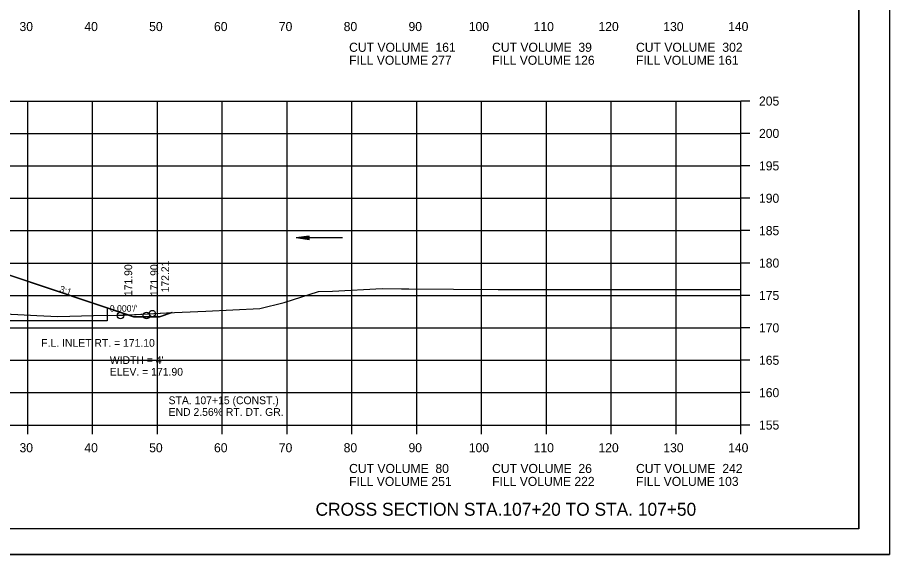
# Model space of a CAD drawing. Extents: x 1372132 to 1372465, y 380083 to 381790.
# Drawn here: x 1372330.4 to 1372464.9, y 380936.8 to 381019.7 of the extents above; entities that cross this region are included whole.
import ezdxf

# ---------------------------------------------------------------- set-up
doc = ezdxf.new("R2010")
doc.units = 0
for name, color, linetype in [('Default', 7, 'Continuous'), ('R_Axis', 7, 'Continuous'), ('R_Axis Annot', 7, 'Continuous'), ('R_Border', 7, 'Continuous'), ('R_Dimension', 7, 'Continuous'), ('R_Draft', 7, 'Continuous'), ('R_Exist Surface', 7, 'Continuous'), ('R_Fin Surface', 7, 'Continuous'), ('R_Grid', 7, 'Continuous'), ('R_No Plot', 7, 'Continuous'), ('R_Xsect Elev', 7, 'Continuous'), ('R_Xsect Slope', 7, 'Continuous')]:
    doc.layers.add(name, color=color, linetype=linetype)

msp = doc.modelspace()

# ---------------------------------------------------------------- linework, layer by layer
at = {"layer": 'Default'}
for p, q in [((1372344.25, 380974.92), (1372344.25, 380972.92)), ((1372344.25, 380972.92), (1372302.01, 380972.88))]:
    msp.add_line(p, q, dxfattribs=at)
at = {"layer": 'R_Axis'}
for p, q in [((1372442.01, 380956.83), (1372442.01, 381006.83)), ((1372443.41, 381006.83), (1372442.01, 381006.83)), ((1372443.41, 381001.83), (1372442.01, 381001.83)), ((1372443.41, 380996.83), (1372442.01, 380996.83)), ((1372443.41, 380991.83), (1372442.01, 380991.83)), ((1372443.41, 380986.83), (1372442.01, 380986.83)), ((1372443.41, 380981.83), (1372442.01, 380981.83)), ((1372443.41, 380976.83), (1372442.01, 380976.83)), ((1372443.41, 380971.83), (1372442.01, 380971.83)), ((1372443.41, 380966.83), (1372442.01, 380966.83)), ((1372443.41, 380961.83), (1372442.01, 380961.83)), ((1372162.01, 380956.83), (1372442.01, 380956.83)), ((1372332.01, 380955.43), (1372332.01, 380956.83)), ((1372342.01, 380955.43), (1372342.01, 380956.83)), ((1372352.01, 380955.43), (1372352.01, 380956.83)), ((1372362.01, 380955.43), (1372362.01, 380956.83)), ((1372372.01, 380955.43), (1372372.01, 380956.83)), ((1372382.01, 380955.43), (1372382.01, 380956.83)), ((1372392.01, 380955.43), (1372392.01, 380956.83)), ((1372402.01, 380955.43), (1372402.01, 380956.83)), ((1372412.01, 380955.43), (1372412.01, 380956.83)), ((1372422.01, 380955.43), (1372422.01, 380956.83)), ((1372432.01, 380955.43), (1372432.01, 380956.83)), ((1372442.01, 380955.43), (1372442.01, 380956.83)), ((1372443.41, 380956.83), (1372442.01, 380956.83))]:
    msp.add_line(p, q, dxfattribs=at)
at = {"layer": 'R_Border'}
for q in [(1372460.19, 381146.29), (1372144.01, 380940.83)]:
    msp.add_line((1372460.19, 380940.83), q, dxfattribs=at)
at = {"layer": 'R_Dimension'}
for p, q in [((1372375.41, 380986), (1372373.41, 380985.7)), ((1372375.41, 380986), (1372373.41, 380985.7)), ((1372375.41, 380985.4), (1372373.41, 380985.7)), ((1372375.41, 380985.4), (1372373.41, 380985.7)), ((1372375.41, 380985.95), (1372373.75, 380985.7)), ((1372375.41, 380985.95), (1372373.75, 380985.7)), ((1372375.41, 380985.45), (1372373.75, 380985.7)), ((1372375.41, 380985.45), (1372373.75, 380985.7)), ((1372375.41, 380985.9), (1372374.09, 380985.7)), ((1372375.41, 380985.9), (1372374.09, 380985.7)), ((1372375.41, 380985.5), (1372374.09, 380985.7)), ((1372375.41, 380985.5), (1372374.09, 380985.7)), ((1372375.41, 380985.85), (1372374.43, 380985.7)), ((1372375.41, 380985.85), (1372374.43, 380985.7)), ((1372375.41, 380985.55), (1372374.43, 380985.7)), ((1372375.41, 380985.55), (1372374.43, 380985.7)), ((1372375.41, 380985.8), (1372374.76, 380985.7)), ((1372375.41, 380985.8), (1372374.76, 380985.7)), ((1372375.41, 380985.6), (1372374.76, 380985.7)), ((1372375.41, 380985.6), (1372374.76, 380985.7)), ((1372375.41, 380985.75), (1372375.1, 380985.7)), ((1372375.41, 380985.75), (1372375.1, 380985.7)), ((1372375.41, 380985.65), (1372375.1, 380985.7)), ((1372375.41, 380985.65), (1372375.1, 380985.7)), ((1372375.41, 380985.4), (1372375.41, 380986)), ((1372375.41, 380985.4), (1372375.41, 380986))]:
    msp.add_line(p, q, dxfattribs=at)
at = {"layer": 'R_Draft'}
msp.add_line((1372380.55, 380985.7), (1372373.41, 380985.7), dxfattribs=at)
at = {"layer": 'R_Exist Surface'}
msp.add_lwpolyline([(1372320.59, 380974.4), (1372333.44, 380973.73), (1372336.66, 380973.6), (1372342.14, 380973.75), (1372345.89, 380973.77), (1372346.54, 380973.79), (1372346.82, 380973.8), (1372353.41, 380974.15), (1372359.48, 380974.38), (1372367.82, 380974.82), (1372371.58, 380975.74), (1372376.85, 380977.43), (1372379.01, 380977.49), (1372386.7, 380977.89), (1372389.66, 380977.86), (1372390.32, 380977.86), (1372390.82, 380977.86), (1372404.58, 380977.77), (1372404.93, 380977.77), (1372417.61, 380977.76), (1372417.98, 380977.77), (1372430.63, 380977.76), (1372431.03, 380977.76), (1372442.01, 380977.75)], dxfattribs=at)
at = {"layer": 'R_Fin Surface'}
msp.add_lwpolyline([(1372247.03, 380973.53), (1372248.08, 380973.18), (1372256.08, 380973.18), (1372277.01, 380980.16), (1372282.65, 380981.57), (1372287.01, 380982.66), (1372291.01, 380982.82), (1372302.01, 380983.04), (1372313.01, 380982.82), (1372317.01, 380982.66), (1372321.38, 380981.57), (1372329.04, 380979.99), (1372348.35, 380973.55), (1372352.35, 380973.55), (1372354.28, 380974.19)], dxfattribs=at)
at = {"layer": 'R_Grid'}
for p, q in [((1372162.01, 381006.83), (1372442.01, 381006.83)), ((1372332.01, 380956.83), (1372332.01, 381006.83)), ((1372342.01, 380956.83), (1372342.01, 381006.83)), ((1372352.01, 380956.83), (1372352.01, 381006.83)), ((1372362.01, 380956.83), (1372362.01, 381006.83)), ((1372372.01, 380956.83), (1372372.01, 381006.83)), ((1372382.01, 380956.83), (1372382.01, 381006.83)), ((1372392.01, 380956.83), (1372392.01, 381006.83)), ((1372402.01, 380956.83), (1372402.01, 381006.83)), ((1372412.01, 380956.83), (1372412.01, 381006.83)), ((1372422.01, 380956.83), (1372422.01, 381006.83)), ((1372432.01, 380956.83), (1372432.01, 381006.83)), ((1372442.01, 380956.83), (1372442.01, 381006.83)), ((1372162.01, 381001.83), (1372442.01, 381001.83)), ((1372162.01, 380996.83), (1372442.01, 380996.83)), ((1372162.01, 380991.83), (1372442.01, 380991.83)), ((1372162.01, 380986.83), (1372442.01, 380986.83)), ((1372162.01, 380981.83), (1372442.01, 380981.83)), ((1372162.01, 380976.83), (1372442.01, 380976.83)), ((1372162.01, 380971.83), (1372442.01, 380971.83)), ((1372162.01, 380966.83), (1372442.01, 380966.83)), ((1372162.01, 380961.83), (1372442.01, 380961.83)), ((1372162.01, 380956.83), (1372442.01, 380956.83))]:
    msp.add_line(p, q, dxfattribs=at)
at = {"layer": 'R_No Plot'}
msp.add_line((1372131.61, 380936.85), (1372464.95, 380936.85), dxfattribs=at)
for points in [[(1372131.61, 381150.18), (1372464.95, 381150.18), (1372464.95, 380936.84), (1372131.61, 380936.84)], [(1372377.93, 381146.29), (1372377.93, 381136.41), (1372413.67, 381136.41), (1372413.67, 381133.49), (1372436.87, 381133.49), (1372436.87, 381109.15), (1372460.19, 381109.15), (1372460.19, 380940.83), (1372144.01, 380940.83), (1372144.01, 381146.29)], [(1372313.5, 380981.73), (1372313.98, 380981.42), (1372314.62, 380981.09), (1372318.17, 380978.23), (1372319.68, 380974.67), (1372319.94, 380974.49), (1372320.09, 380974.42), (1372320.59, 380974.4), (1372333.44, 380973.73), (1372336.66, 380973.6), (1372342.14, 380973.75), (1372345.89, 380973.77), (1372346.54, 380973.79), (1372346.82, 380973.8), (1372347.5, 380973.83), (1372329.04, 380979.99), (1372321.38, 380981.57)], [(1372347.5, 380973.83), (1372353.41, 380974.15), (1372354.23, 380974.18), (1372352.35, 380973.55), (1372348.35, 380973.55)], [(1372354.23, 380974.18), (1372354.28, 380974.18), (1372354.28, 380974.19)]]:
    msp.add_lwpolyline(points, close=True, dxfattribs=at)
for centre in [(1372351.24, 380974.03), (1372346.33, 380973.73), (1372350.33, 380973.73)]:
    msp.add_circle(centre, 0.5, dxfattribs=at)

# ---------------------------------------------------------------- texts
at = {"layer": 'Default'}
msp.add_text('F.L. INLET RT. = 171.10', height=1.2, dxfattribs=at).set_placement((1372334.1, 380968.91))
at = {"layer": 'R_Axis Annot'}
for s, p in [('30', (1372330.75, 381017.63)), ('40', (1372340.75, 381017.63)), ('50', (1372350.75, 381017.63)), ('60', (1372360.75, 381017.63)), ('70', (1372370.75, 381017.63)), ('80', (1372380.75, 381017.63)), ('90', (1372390.75, 381017.63)), ('100', (1372400.05, 381017.63)), ('110', (1372410.05, 381017.63)), ('120', (1372420.05, 381017.63)), ('130', (1372430.05, 381017.63)), ('140', (1372440.05, 381017.63)), ('CUT VOLUME  161', (1372381.59, 381014.43)), ('CUT VOLUME  39', (1372403.64, 381014.43)), ('CUT VOLUME  302', (1372425.84, 381014.43)), ('FILL VOLUME 277', (1372381.59, 381012.43)), ('FILL VOLUME 126', (1372403.64, 381012.43)), ('FILL VOLUME 161', (1372425.84, 381012.43)), ('205', (1372444.81, 381006.13)), ('200', (1372444.81, 381001.13)), ('195', (1372444.81, 380996.13)), ('190', (1372444.81, 380991.13)), ('185', (1372444.81, 380986.13)), ('180', (1372444.81, 380981.13)), ('175', (1372444.81, 380976.13)), ('170', (1372444.81, 380971.13)), ('165', (1372444.81, 380966.13)), ('160', (1372444.81, 380961.13)), ('155', (1372444.81, 380956.13)), ('30', (1372330.75, 380952.63)), ('40', (1372340.75, 380952.63)), ('50', (1372350.75, 380952.63)), ('60', (1372360.75, 380952.63)), ('70', (1372370.75, 380952.63)), ('80', (1372380.75, 380952.63)), ('90', (1372390.75, 380952.63)), ('100', (1372400.05, 380952.63)), ('110', (1372410.05, 380952.63)), ('120', (1372420.05, 380952.63)), ('130', (1372430.05, 380952.63)), ('140', (1372440.05, 380952.63)), ('CUT VOLUME  80', (1372381.59, 380949.43)), ('CUT VOLUME  26', (1372403.64, 380949.43)), ('CUT VOLUME  242', (1372425.84, 380949.43)), ('FILL VOLUME 251', (1372381.59, 380947.43)), ('FILL VOLUME 222', (1372403.64, 380947.43)), ('FILL VOLUME 103', (1372425.84, 380947.43))]:
    msp.add_text(s, height=1.4, dxfattribs=at).set_placement(p)
at = {"layer": 'R_Dimension'}
for s, p in [("WIDTH = 4'", (1372344.68, 380966.25)), ('ELEV. = 171.90', (1372344.68, 380964.45))]:
    msp.add_text(s, height=1.2, dxfattribs=at).set_placement(p)
at = {"layer": 'R_Draft'}
for s, height, p in [('STA. 107+15 (CONST.)', 1.2, (1372353.75, 380960.05)), ('END 2.56% RT. DT. GR.', 1.2, (1372353.75, 380958.25)), ('CROSS SECTION STA.107+20 TO STA. 107+50', 2, (1372376.41, 380942.83))]:
    msp.add_text(s, height=height, dxfattribs=at).set_placement(p)
at = {"layer": 'R_Xsect Elev'}
for s, p in [('171.90', (1372348.13, 380976.73)), ('171.90', (1372352.13, 380976.73)), ('172.21', (1372353.83, 380977.3))]:
    msp.add_text(s, height=1.2, rotation=90, dxfattribs=at).set_placement(p)
at = {"layer": 'R_Xsect Slope'}
for s, rotation, p in [('3:1', 341.5668, (1372336.83, 380977.42)), ("0.000'/'", 360, (1372344.68, 380974.33))]:
    msp.add_text(s, height=1, rotation=rotation, dxfattribs=at).set_placement(p)

doc.saveas('drawing.dxf')
